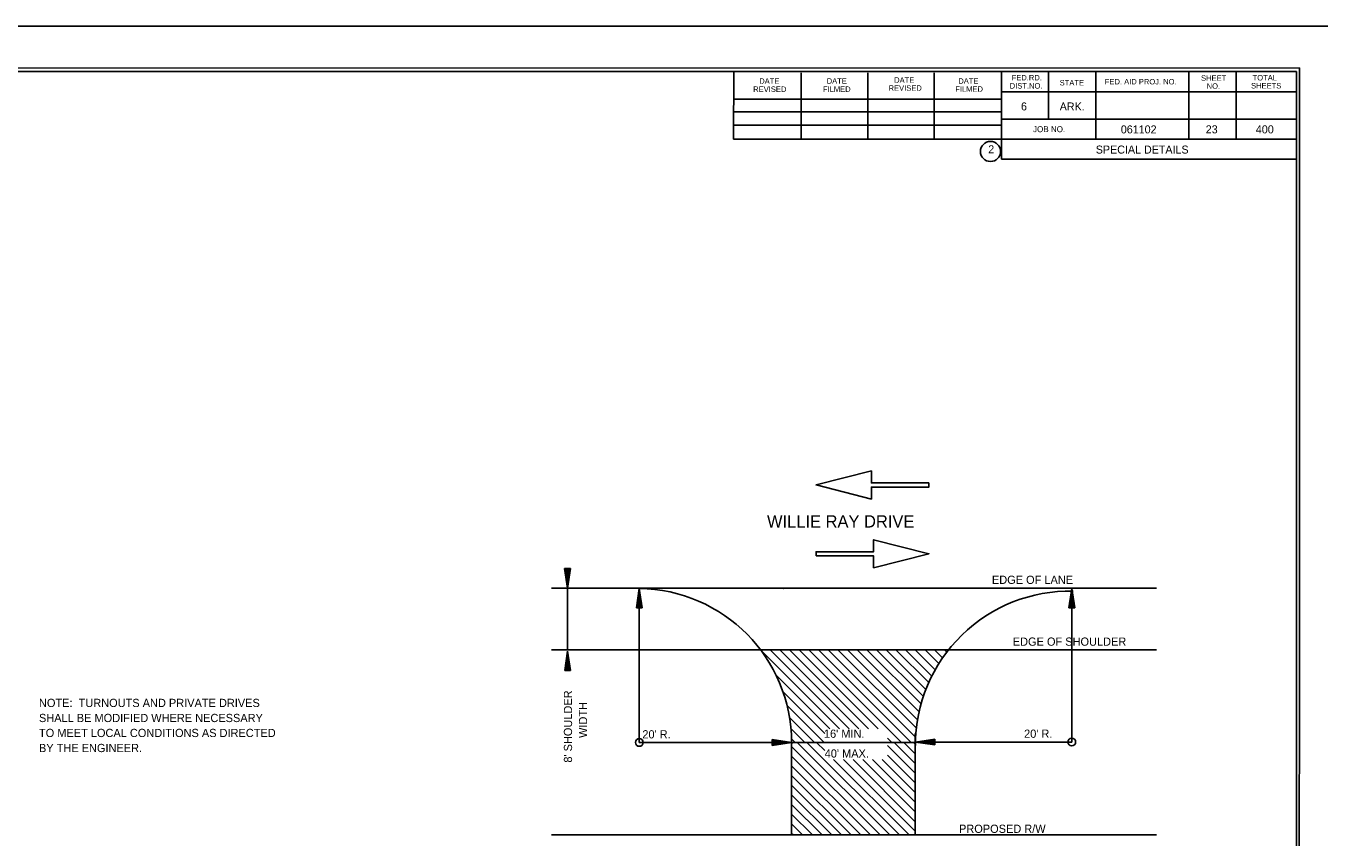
# Model space of a CAD drawing. Extents: x 714919 to 718439, y 1619644 to 1621844.
# Drawn here: x 716536 to 718439, y 1620657 to 1621844 of the extents above; entities that cross this region are included whole.
import ezdxf

# ---------------------------------------------------------------- set-up
doc = ezdxf.new("R2010")
doc.units = 0
for name, color, linetype in [('Default', 7, 'Continuous'), ('Drainage', 7, 'Continuous'), ('R_Border', 7, 'Continuous'), ('R_No Plot', 7, 'Continuous')]:
    doc.layers.add(name, color=color, linetype=linetype)

msp = doc.modelspace()

# ---------------------------------------------------------------- linework, layer by layer
at = {"layer": 'Default'}
for p, q in [((717323.4, 1621050.5), (717327.6, 1621022.2)), ((717331.9, 1621050.5), (717323.4, 1621050.5)), ((717324, 1621050.5), (717327.6, 1621026.9)), ((717324.8, 1621050.5), (717327.6, 1621031.7)), ((717325.5, 1621050.5), (717327.6, 1621036.5)), ((717326.2, 1621050.5), (717327.6, 1621041.3)), ((717326.9, 1621050.5), (717327.6, 1621045.9)), ((717331.9, 1621050.5), (717327.6, 1621022.2)), ((717328.9, 1621050.5), (717327.6, 1621041.3)), ((717330.5, 1621050.5), (717327.6, 1621031.7)), ((717331.2, 1621050.5), (717327.6, 1621026.9)), ((717329.7, 1621050.5), (717327.6, 1621036.5)), ((717328.3, 1621050.5), (717327.6, 1621045.9)), ((717304.3, 1621022.2), (718188.4, 1621022.2)), ((717327.7, 1620931.8), (717327.7, 1621022.2)), ((717428.3, 1620993.2), (717432.5, 1621021.5)), ((717429, 1620993.2), (717432.5, 1621016.7)), ((717436.7, 1620993.2), (717432.5, 1621021.5)), ((717432.5, 1620796.4), (717432.5, 1621021.5)), ((717436.1, 1620993.2), (717432.5, 1621016.7)), ((717642.8, 1621021.2), (717643.2, 1621022.5)), ((717643.2, 1621022.1), (717642.8, 1621021.2)), ((717642.8, 1621021.2), (717643.2, 1621021.6)), ((718060.4, 1620993.3), (718064.6, 1621021.6)), ((718061.1, 1620993.3), (718064.6, 1621016.8)), ((718068.9, 1620993.3), (718064.6, 1621021.6)), ((718064.6, 1620797), (718064.6, 1621021.6)), ((718068.1, 1620993.3), (718064.6, 1621016.8)), ((717428.3, 1620993.2), (717436.7, 1620993.2)), ((717429.7, 1620993.2), (717432.5, 1621011.8)), ((717430.4, 1620993.2), (717432.5, 1621007.2)), ((717431.2, 1620993.2), (717432.5, 1621002.4)), ((717431.8, 1620993.2), (717432.5, 1620997.7)), ((717435.3, 1620993.2), (717432.5, 1621011.8)), ((717434.6, 1620993.2), (717432.5, 1621007.2)), ((717433.9, 1620993.2), (717432.5, 1621002.4)), ((717433.2, 1620993.2), (717432.5, 1620997.7)), ((718060.4, 1620993.3), (718068.9, 1620993.3)), ((718061.8, 1620993.3), (718064.6, 1621012)), ((718062.5, 1620993.3), (718064.6, 1621007.3)), ((718063.2, 1620993.3), (718064.6, 1621002.5)), ((718063.9, 1620993.3), (718064.6, 1620997.8)), ((718067.4, 1620993.3), (718064.6, 1621012)), ((718066.7, 1620993.3), (718064.6, 1621007.3)), ((718066, 1620993.3), (718064.6, 1621002.5)), ((718065.3, 1620993.3), (718064.6, 1620997.8)), ((717304.3, 1620931.8), (718188.4, 1620931.8)), ((717323.6, 1620901.7), (717327.8, 1620930)), ((717324.3, 1620901.7), (717327.8, 1620925.2)), ((717325, 1620901.7), (717327.8, 1620920.4)), ((717332, 1620901.7), (717327.8, 1620930)), ((717331.3, 1620901.7), (717327.8, 1620925.2)), ((717330.6, 1620901.7), (717327.8, 1620920.4)), ((717725.2, 1620816.2), (717609.7, 1620931.8)), ((717739.4, 1620816.2), (717623.8, 1620931.8)), ((717753.5, 1620816.2), (717638, 1620931.8)), ((717767.7, 1620816.2), (717652.1, 1620931.8)), ((717781.8, 1620816.2), (717666.2, 1620931.8)), ((717815.7, 1620796.5), (717680.4, 1620931.8)), ((717829.5, 1620796.9), (717694.5, 1620931.8)), ((717835.7, 1620804.7), (717708.7, 1620931.8)), ((717837.5, 1620817.2), (717722.8, 1620931.8)), ((717839.2, 1620829.6), (717737, 1620931.8)), ((717841.5, 1620841.4), (717751.1, 1620931.8)), ((717844.4, 1620852.7), (717765.2, 1620931.8)), ((717847.7, 1620863.5), (717779.4, 1620931.8)), ((717851.4, 1620873.9), (717793.5, 1620931.8)), ((717855.6, 1620883.9), (717807.7, 1620931.8)), ((717860.1, 1620893.5), (717821.8, 1620931.8)), ((717865, 1620902.7), (717835.9, 1620931.8)), ((717870.3, 1620911.6), (717850.1, 1620931.8)), ((717875.9, 1620920.1), (717864.2, 1620931.8)), ((717881.9, 1620928.3), (717878.4, 1620931.8)), ((717323.6, 1620901.7), (717332, 1620901.7)), ((717325.6, 1620901.7), (717327.8, 1620915.7)), ((717326.4, 1620901.7), (717327.8, 1620910.9)), ((717327.1, 1620901.7), (717327.8, 1620906.2)), ((717329.8, 1620901.7), (717327.8, 1620915.7)), ((717329.2, 1620901.7), (717327.8, 1620910.9)), ((717328.4, 1620901.7), (717327.8, 1620906.2)), ((717711.1, 1620816.2), (717632, 1620895.3)), ((717703.5, 1620809.7), (717642.3, 1620870.9)), ((717702.7, 1620796.4), (717648.3, 1620850.7)), ((717688.5, 1620796.4), (717652, 1620832.9)), ((717674.4, 1620796.4), (717654.1, 1620816.7)), ((717655, 1620806.4), (717655, 1620795.8)), ((717835.7, 1620809.4), (717835.7, 1620796.5)), ((717655, 1620796.4), (717432.5, 1620796.4)), ((717626.7, 1620800.6), (717655, 1620796.4)), ((717626.7, 1620800.6), (717626.7, 1620792.1)), ((717626.7, 1620799.9), (717650.2, 1620796.4)), ((717626.7, 1620799.2), (717645.4, 1620796.4)), ((717626.7, 1620798.4), (717640.7, 1620796.4)), ((717626.7, 1620797.8), (717635.9, 1620796.4)), ((717626.7, 1620797), (717631.2, 1620796.4)), ((717626.7, 1620792.1), (717655, 1620796.4)), ((717626.7, 1620795), (717635.9, 1620796.4)), ((717626.7, 1620793.5), (717645.4, 1620796.4)), ((717626.7, 1620792.8), (717650.2, 1620796.4)), ((717626.7, 1620794.3), (717640.7, 1620796.4)), ((717626.7, 1620795.7), (717631.2, 1620796.4)), ((717660.2, 1620796.4), (717655, 1620801.6)), ((717655, 1620796.4), (717655, 1620661.2)), ((717655, 1620796.4), (717814.3, 1620796.4)), ((717784.4, 1620661.2), (717655, 1620790.6)), ((717798.6, 1620661.2), (717663.4, 1620796.4)), ((717812.7, 1620661.2), (717677.5, 1620796.4)), ((717703.5, 1620784.6), (717691.7, 1620796.4)), ((717801.6, 1620796.4), (717795.3, 1620802.7)), ((717835.7, 1620751.3), (717795.3, 1620791.8)), ((717835.7, 1620765.5), (717804.8, 1620796.4)), ((717809.9, 1620796.4), (717836.8, 1620796.4)), ((717835.7, 1620779.6), (717818.7, 1620796.6)), ((717835.7, 1620793.7), (717832.6, 1620796.9)), ((717835.7, 1620661), (717835.7, 1620797)), ((717864.3, 1620801.2), (717836.1, 1620797)), ((717864.3, 1620792.8), (717836.1, 1620797)), ((717836.1, 1620797), (718064.6, 1620797)), ((717864.3, 1620800.6), (717840.8, 1620797)), ((717864.3, 1620793.5), (717840.8, 1620797)), ((717864.3, 1620799.9), (717845.7, 1620797)), ((717864.3, 1620794.2), (717845.7, 1620797)), ((717864.3, 1620799.1), (717850.4, 1620797)), ((717864.3, 1620795), (717850.4, 1620797)), ((717864.3, 1620798.5), (717855.2, 1620797)), ((717864.3, 1620795.7), (717855.2, 1620797)), ((717864.3, 1620797.7), (717859.9, 1620797)), ((717864.3, 1620796.3), (717859.9, 1620797)), ((717864.3, 1620792.8), (717864.3, 1620801.2)), ((717770.3, 1620661.2), (717655, 1620776.5)), ((717826.9, 1620661.2), (717716.6, 1620771.4)), ((717835.7, 1620666.5), (717730.8, 1620771.4)), ((717835.7, 1620680.6), (717744.9, 1620771.4)), ((717835.7, 1620694.8), (717759.1, 1620771.4)), ((717835.7, 1620708.9), (717773.2, 1620771.4)), ((717835.7, 1620723), (717787.3, 1620771.4)), ((717835.7, 1620737.2), (717795.3, 1620777.6)), ((717756.2, 1620661.2), (717655, 1620762.3)), ((717742, 1620661.2), (717655, 1620748.2)), ((717727.9, 1620661.2), (717655, 1620734.1)), ((717713.7, 1620661.2), (717655, 1620719.9)), ((717699.6, 1620661.2), (717655, 1620705.8)), ((717685.5, 1620661.2), (717655, 1620691.7)), ((717671.3, 1620661.2), (717655, 1620677.5)), ((717304.3, 1620661.2), (718188.4, 1620661.2)), ((717657.2, 1620661.2), (717655, 1620663.4))]:
    msp.add_line(p, q, dxfattribs=at)
for points in [[(717654.9, 1620803.4), (717655.2, 1620803)], [(717655.2, 1620795.6), (717656.4, 1620794.5)]]:
    msp.add_lwpolyline(points, dxfattribs=at)
for centre in [(717432.5, 1620796.4), (718064.6, 1620797)]:
    msp.add_circle(centre, 5.65, dxfattribs=at)
for centre, radius, start, end in [((717429.7, 1620796.1), 225.4, 0.0764, 89.2743), ((718061.5, 1620792.1), 225.5, 88.7538, 180)]:
    msp.add_arc(centre, radius, start, end, dxfattribs=at)
at = {"layer": 'Drainage'}
for points in [[(717855.7, 1621175.8), (717771.8, 1621175.8), (717771.8, 1621193.3), (717691, 1621172.8), (717771.8, 1621152.3), (717771.8, 1621169.8), (717855.7, 1621169.8)], [(717691, 1621069.2), (717774.9, 1621069.2), (717774.9, 1621051.7), (717855.7, 1621072.2), (717774.9, 1621092.8), (717774.9, 1621075.3), (717691, 1621075.3)]]:
    msp.add_lwpolyline(points, close=True, dxfattribs=at)
at = {"layer": 'R_Border'}
for p, q in [((718439, 1621843.8), (714919, 1621843.5)), ((715231.3, 1621777.1), (718393.1, 1621777.1)), ((717570.4, 1621678.3), (717570.5, 1621777.2)), ((717668.9, 1621678.3), (717669.1, 1621775.2)), ((717766.6, 1621678.2), (717766.6, 1621775.2)), ((717863.5, 1621678.3), (717863.5, 1621775.1)), ((717961.8, 1621777.1), (717962, 1621649.1)), ((718030.5, 1621777), (718030.4, 1621707.7)), ((718099.8, 1621777.1), (718099.8, 1621678.4)), ((718235.5, 1621777.2), (718235.5, 1621678.5)), ((718305, 1621777.3), (718305, 1621678.3)), ((718393.2, 1619722.5), (718393.1, 1621777.1)), ((717570.3, 1621736.9), (717961.9, 1621736.9)), ((718393, 1621747.5), (717962.1, 1621747.6)), ((718393.1, 1621747.9), (718393.1, 1621747.9)), ((717570.4, 1621718.3), (717961.9, 1621718.3)), ((717570.4, 1621678.3), (717570.4, 1621699)), ((717570.4, 1621699), (717962.1, 1621699)), ((718393.1, 1621707.7), (717962, 1621707.7)), ((717991.6, 1621707.7), (718393.1, 1621707.7)), ((718393.1, 1621678.3), (717570.4, 1621678.3)), ((717962, 1621649.1), (718393.1, 1621649.2))]:
    msp.add_line(p, q, dxfattribs=at)
msp.add_circle((717945.8, 1621660.4), 14.7, dxfattribs=at)
at = {"layer": 'R_No Plot'}
msp.add_lwpolyline([(715227.2, 1619717.3), (718397.1, 1619717.4), (718397.2, 1621782.5), (715227.1, 1621782.3)], close=True, dxfattribs=at)

# ---------------------------------------------------------------- texts
at = {"layer": 'Default'}
for s, height, p in [('WILLIE RAY DRIVE', 18, (717619.2, 1621110.6)), ('EDGE OF LANE', 12, (717947.9, 1621028.2)), ('EDGE OF SHOULDER', 12, (717978.4, 1620937.8)), ('NOTE:  TURNOUTS AND PRIVATE DRIVES', 12, (716555.2, 1620848.2)), ('SHALL BE MODIFIED WHERE NECESSARY', 12, (716555.2, 1620826.2)), ('TO MEET LOCAL CONDITIONS AS DIRECTED', 12, (716555.2, 1620804.3)), ("20' R.", 12, (717437, 1620802.3)), ("16' MIN.", 12, (717702.4, 1620803.2)), ("20' R.", 12, (717994.9, 1620803.2)), ('BY THE ENGINEER.', 12, (716555.2, 1620782.3)), ("40' MAX.", 12, (717703.5, 1620774.3)), ('PROPOSED R/W', 12, (717899.8, 1620664.2))]:
    msp.add_text(s, height=height, dxfattribs=at).set_placement(p)
for s, p in [("8' SHOULDER", (717334.3, 1620766.9)), ('WIDTH', (717356.3, 1620803))]:
    msp.add_text(s, height=12, rotation=90, dxfattribs=at).set_placement(p)
at = {"layer": 'R_Border'}
for s, height, rotation, p in [('REVISED', 8, 0.0017, (717599, 1621747.4)), ('DATE', 8, 0.0017, (717607.8, 1621759.3)), ('FILMED', 8, 0.0017, (717700.9, 1621747.5)), ('DATE', 8, 0.0017, (717706.4, 1621759.4)), ('REVISED', 8, 0.0017, (717796.9, 1621749.1)), ('DATE', 8, 0.0017, (717805, 1621760.8)), ('FILMED', 8, 0.0017, (717894.3, 1621747.6)), ('DATE', 8, 0.0017, (717898.8, 1621759.4)), ('DIST.NO.', 8, 0.0017, (717973.9, 1621752.3)), ('FED.RD.', 8, 0.0017, (717976.7, 1621764.3)), ('STATE', 8, 0.0017, (718046.9, 1621756.9)), ('FED. AID PROJ. NO.', 8, 0.0017, (718112.9, 1621758.4)), ('SHEET', 8, 0.0017, (718253.5, 1621763.7)), ('NO.', 8, 0.0017, (718261.7, 1621752)), ('SHEETS', 8, 0.0017, (718326.6, 1621752.5)), ('TOTAL', 8, 0.0017, (718328.9, 1621764.2)), ('6', 11.7, 0.0017, (717990.4, 1621720.4)), ('ARK.', 11.72, 0.0017, (718047, 1621720.3)), ('JOB NO.', 8.79, 0.0017, (718008, 1621688.6)), ('061102', 11.7, 0.0018, (718136.3, 1621686.8)), ('23', 11.7, 0.0018, (718260.4, 1621686.9)), ('400', 11.79, 0.0018, (718333.5, 1621686.8)), ('2', 11.7, 0.0017, (717942.5, 1621657.7)), ('SPECIAL DETAILS', 11.7, 0.0018, (718099.7, 1621657.3))]:
    msp.add_text(s, height=height, rotation=rotation, dxfattribs=at).set_placement(p)

doc.saveas('drawing.dxf')
